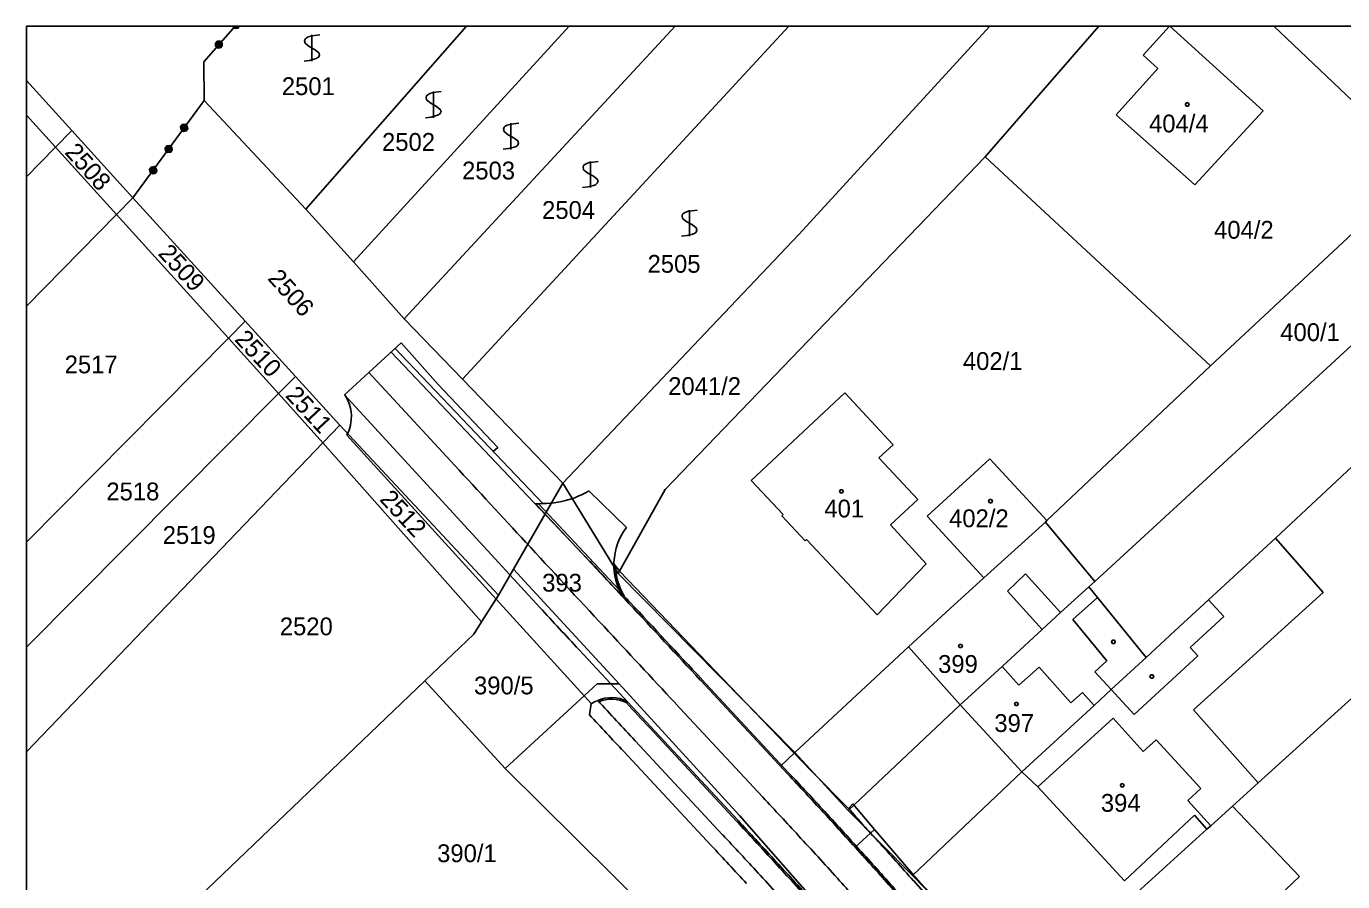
# Model space of a CAD drawing. Extents: x -639621 to -639329, y -1192893 to -1192488.
# Drawn here: x -639621.3 to -639495.6, y -1192569.5 to -1192487.8 of the extents above; entities that cross this region are included whole.
import ezdxf

# ---------------------------------------------------------------- set-up
doc = ezdxf.new("R2010")
doc.units = 0
for name, color, linetype in [('Vrstva 1', 7, 'Continuous'), ('Vrstva 19', 7, 'Continuous'), ('Vrstva 2', 7, 'Continuous'), ('Vrstva 20', 7, 'Continuous'), ('Vrstva 21', 7, 'Continuous'), ('Vrstva 22', 7, 'Continuous'), ('Vrstva 3', 7, 'Continuous'), ('Vrstva 4', 7, 'Continuous'), ('Vrstva 5', 7, 'Continuous'), ('Vrstva 61', 7, 'Continuous')]:
    doc.layers.add(name, color=color, linetype=linetype)

msp = doc.modelspace()

# ---------------------------------------------------------------- linework, layer by layer
at = {"layer": 'Vrstva 1'}
for p, q in [((-639601.33, -1192487.83), (-639604.33, -1192491.21)), ((-639579.25, -1192487.83), (-639594.57, -1192505.29)), ((-639590.01, -1192510.33), (-639569.44, -1192487.83)), ((-639585.18, -1192515.76), (-639559.3, -1192487.83)), ((-639548.46, -1192487.83), (-639579.63, -1192521.52)), ((-639547.5, -1192507.7), (-639529.28, -1192487.83)), ((-639529.73, -1192500.3), (-639518.86, -1192487.83)), ((-639512.13, -1192487.83), (-639514.63, -1192490.58)), ((-639503.19, -1192495.91), (-639512.08, -1192487.83)), ((-639502.15, -1192487.83), (-639487.95, -1192501.33)), ((-639514.63, -1192490.58), (-639513.22, -1192491.87)), ((-639604.33, -1192491.21), (-639604.27, -1192494.9)), ((-639513.22, -1192491.87), (-639517.21, -1192496.27)), ((-639616.93, -1192497.77), (-639621.26, -1192493.01)), ((-639611.08, -1192504.2), (-639604.27, -1192494.9)), ((-639604.27, -1192494.9), (-639594.57, -1192505.29)), ((-639509.7, -1192502.95), (-639503.19, -1192495.91)), ((-639457.17, -1192494.75), (-639502, -1192536.7)), ((-639621.26, -1192496.32), (-639618.49, -1192499.37)), ((-639517.21, -1192496.27), (-639509.7, -1192502.95)), ((-639618.49, -1192499.37), (-639616.93, -1192497.77)), ((-639611.08, -1192504.2), (-639616.93, -1192497.77)), ((-639618.49, -1192499.37), (-639621.26, -1192502.2)), ((-639618.49, -1192499.37), (-639612.65, -1192505.79)), ((-639529.73, -1192500.3), (-639560.27, -1192532.04)), ((-639529.73, -1192500.3), (-639508.19, -1192520.25)), ((-639508.19, -1192520.25), (-639487.95, -1192501.33)), ((-639612.65, -1192505.79), (-639611.08, -1192504.2)), ((-639600.36, -1192515.98), (-639611.08, -1192504.2)), ((-639621.26, -1192514.55), (-639612.65, -1192505.79)), ((-639612.65, -1192505.79), (-639601.96, -1192517.59)), ((-639594.57, -1192505.29), (-639590.01, -1192510.33)), ((-639519.26, -1192540.82), (-639482.08, -1192506.67)), ((-639570.05, -1192531.45), (-639547.5, -1192507.7)), ((-639590.01, -1192510.33), (-639585.18, -1192515.76)), ((-639601.96, -1192517.59), (-639600.36, -1192515.98)), ((-639595.57, -1192521.25), (-639600.36, -1192515.98)), ((-639579.63, -1192521.52), (-639585.18, -1192515.76)), ((-639601.96, -1192517.59), (-639621.26, -1192537.09)), ((-639601.96, -1192517.59), (-639597.2, -1192522.89)), ((-639523.82, -1192535.02), (-639508.19, -1192520.25)), ((-639597.2, -1192522.89), (-639595.57, -1192521.25)), ((-639591.33, -1192525.9), (-639595.57, -1192521.25)), ((-639579.63, -1192521.52), (-639570.05, -1192531.45)), ((-639621.26, -1192547.09), (-639597.2, -1192522.89)), ((-639597.2, -1192522.89), (-639592.96, -1192527.6)), ((-639543.13, -1192522.82), (-639552.05, -1192531.18)), ((-639538.51, -1192527.78), (-639543.13, -1192522.82)), ((-639591.33, -1192525.9), (-639592.96, -1192527.6)), ((-639576.18, -1192542.14), (-639591.33, -1192525.9)), ((-639592.96, -1192527.6), (-639621.26, -1192557.11)), ((-639577.8, -1192544.69), (-639592.96, -1192527.6)), ((-639539.86, -1192529.04), (-639538.51, -1192527.78)), ((-639536.15, -1192533.02), (-639539.86, -1192529.04)), ((-639535.25, -1192534.61), (-639529.27, -1192529.13)), ((-639529.27, -1192529.13), (-639523.82, -1192535.02)), ((-639570.05, -1192531.45), (-639574.76, -1192539.66)), ((-639564.74, -1192540.08), (-639570.05, -1192531.45)), ((-639560.27, -1192532.04), (-639564.74, -1192540.08)), ((-639552.05, -1192531.18), (-639548.99, -1192534.45)), ((-639538.75, -1192535.44), (-639536.15, -1192533.02)), ((-639548.99, -1192534.45), (-639549.12, -1192534.56)), ((-639549.12, -1192534.56), (-639546.9, -1192536.94)), ((-639529.84, -1192540.49), (-639535.25, -1192534.61)), ((-639535.35, -1192539.16), (-639538.75, -1192535.44)), ((-639529.84, -1192540.49), (-639523.97, -1192535.16)), ((-639523.97, -1192535.16), (-639523.82, -1192535.02)), ((-639523.97, -1192535.16), (-639519.26, -1192540.82)), ((-639546.77, -1192536.83), (-639546.9, -1192536.94)), ((-639546.77, -1192536.83), (-639540.04, -1192544.03)), ((-639502, -1192536.7), (-639508.39, -1192542.59)), ((-639502, -1192536.7), (-639497.45, -1192541.88)), ((-639574.76, -1192539.66), (-639576.18, -1192542.14)), ((-639574.76, -1192539.66), (-639573.32, -1192541.22)), ((-639540.04, -1192544.03), (-639535.35, -1192539.16)), ((-639547.9, -1192557.16), (-639564.74, -1192540.08)), ((-639533.05, -1192543.41), (-639529.84, -1192540.49)), ((-639519.83, -1192541.35), (-639519.26, -1192540.82)), ((-639576.18, -1192542.14), (-639577.8, -1192544.69)), ((-639564.65, -1192550.62), (-639573.32, -1192541.22)), ((-639522.51, -1192543.81), (-639519.83, -1192541.35)), ((-639519.83, -1192541.35), (-639519, -1192542.37)), ((-639519, -1192542.37), (-639514.35, -1192548.08)), ((-639509.82, -1192553.1), (-639497.45, -1192541.88)), ((-639537.05, -1192547.08), (-639533.05, -1192543.41)), ((-639508.39, -1192542.59), (-639511.62, -1192545.56)), ((-639577.8, -1192544.69), (-639578.54, -1192545.86)), ((-639524.28, -1192545.43), (-639522.51, -1192543.81)), ((-639578.54, -1192545.86), (-639583.2, -1192550.31)), ((-639528.1, -1192548.94), (-639524.28, -1192545.43)), ((-639511.62, -1192545.56), (-639514.35, -1192548.08)), ((-639503.65, -1192560.07), (-639487.05, -1192545.04)), ((-639547.9, -1192557.16), (-639537.05, -1192547.08)), ((-639514.35, -1192548.08), (-639517.68, -1192551.15)), ((-639532.09, -1192552.6), (-639528.1, -1192548.94)), ((-639583.2, -1192550.31), (-639621.26, -1192586.7)), ((-639583.2, -1192550.31), (-639575.54, -1192558.69)), ((-639575.54, -1192558.69), (-639566.76, -1192550.59)), ((-639564.65, -1192550.62), (-639566.76, -1192550.59)), ((-639553.16, -1192563.18), (-639564.65, -1192550.62)), ((-639517.68, -1192551.15), (-639519.32, -1192552.66)), ((-639542.8, -1192562.7), (-639532.09, -1192552.6)), ((-639519.32, -1192552.66), (-639526.21, -1192559.01)), ((-639503.65, -1192560.07), (-639509.82, -1192553.1)), ((-639542.8, -1192562.7), (-639547.9, -1192557.16)), ((-639561.85, -1192572.23), (-639575.54, -1192558.69)), ((-639526.21, -1192559.01), (-639536.67, -1192568.89)), ((-639526.21, -1192559.01), (-639524.7, -1192560.45)), ((-639524.7, -1192560.45), (-639516.41, -1192569.42)), ((-639506.1, -1192562.29), (-639503.65, -1192560.07)), ((-639508.17, -1192564.16), (-639506.1, -1192562.29)), ((-639506.1, -1192562.29), (-639499.72, -1192569.01)), ((-639534.95, -1192583.89), (-639553.16, -1192563.18)), ((-639536.67, -1192568.89), (-639542.8, -1192562.7)), ((-639516.41, -1192569.42), (-639509.74, -1192563.15)), ((-639508.54, -1192564.49), (-639509.74, -1192563.15)), ((-639515.21, -1192570.53), (-639508.54, -1192564.49)), ((-639508.54, -1192564.49), (-639508.17, -1192564.16)), ((-639525.7, -1192580.15), (-639536.67, -1192568.89)), ((-639499.72, -1192569.01), (-639502.36, -1192571.52))]:
    msp.add_line(p, q, dxfattribs=at)
for points in [[(-639601.06, -1192488.01), (-639601.33, -1192488.03), (-639601.53, -1192487.85), (-639601.53, -1192487.83)], [(-639601.49, -1192487.83), (-639601.49, -1192487.83), (-639601.49, -1192487.83)], [(-639601.28, -1192487.83), (-639601.37, -1192487.94), (-639601.43, -1192487.89), (-639601.38, -1192487.83)], [(-639601.06, -1192487.83), (-639601.2, -1192487.99), (-639601.31, -1192487.99), (-639601.17, -1192487.83)], [(-639600.9, -1192487.83), (-639601.06, -1192488.01), (-639601.08, -1192487.98), (-639600.95, -1192487.83)], [(-639602.73, -1192489.89), (-639603, -1192489.91), (-639603.2, -1192489.73), (-639603.21, -1192489.46), (-639603.04, -1192489.26), (-639602.77, -1192489.24), (-639602.57, -1192489.42), (-639602.55, -1192489.69), (-639602.73, -1192489.89), (-639602.73, -1192489.83), (-639602.57, -1192489.66), (-639602.59, -1192489.56), (-639602.84, -1192489.84), (-639602.96, -1192489.85), (-639602.61, -1192489.46), (-639602.67, -1192489.41), (-639603.02, -1192489.79), (-639603.08, -1192489.74), (-639602.73, -1192489.35), (-639602.79, -1192489.29), (-639603.13, -1192489.68), (-639603.16, -1192489.6), (-639602.89, -1192489.29), (-639602.98, -1192489.28), (-639603.14, -1192489.46)], [(-639606.37, -1192497.22), (-639606.1, -1192497.18), (-639605.89, -1192497.34), (-639605.84, -1192497.61), (-639606, -1192497.82), (-639606.27, -1192497.86), (-639606.49, -1192497.71), (-639606.53, -1192497.44), (-639606.37, -1192497.22), (-639606.36, -1192497.28), (-639606.5, -1192497.47), (-639606.47, -1192497.57), (-639606.25, -1192497.26), (-639606.14, -1192497.24), (-639606.44, -1192497.66), (-639606.38, -1192497.71), (-639606.07, -1192497.29), (-639606.01, -1192497.34), (-639606.31, -1192497.76), (-639606.26, -1192497.81), (-639605.95, -1192497.39), (-639605.91, -1192497.47), (-639606.15, -1192497.8), (-639606.06, -1192497.81), (-639605.91, -1192497.62)], [(-639607.85, -1192499.25), (-639607.58, -1192499.21), (-639607.37, -1192499.37), (-639607.33, -1192499.63), (-639607.48, -1192499.85), (-639607.75, -1192499.89), (-639607.97, -1192499.73), (-639608.01, -1192499.47), (-639607.85, -1192499.25), (-639607.82, -1192499.28), (-639607.97, -1192499.47), (-639607.95, -1192499.58), (-639607.71, -1192499.26), (-639607.6, -1192499.25), (-639607.93, -1192499.7), (-639607.87, -1192499.74), (-639607.54, -1192499.29), (-639607.47, -1192499.34), (-639607.8, -1192499.79), (-639607.74, -1192499.84), (-639607.41, -1192499.39), (-639607.39, -1192499.5), (-639607.63, -1192499.82), (-639607.51, -1192499.8), (-639607.37, -1192499.61)], [(-639609.33, -1192501.27), (-639609.07, -1192501.23), (-639608.85, -1192501.39), (-639608.81, -1192501.66), (-639608.97, -1192501.88), (-639609.23, -1192501.92), (-639609.45, -1192501.76), (-639609.49, -1192501.49), (-639609.33, -1192501.27), (-639609.3, -1192501.29), (-639609.44, -1192501.48), (-639609.42, -1192501.59), (-639609.18, -1192501.27), (-639609.08, -1192501.27), (-639609.4, -1192501.71), (-639609.34, -1192501.75), (-639609.02, -1192501.33), (-639608.95, -1192501.36), (-639609.27, -1192501.79), (-639609.2, -1192501.84), (-639608.89, -1192501.41), (-639608.85, -1192501.5), (-639609.11, -1192501.85), (-639609, -1192501.84), (-639608.84, -1192501.61)]]:
    msp.add_lwpolyline(points, dxfattribs=at)
at = {"layer": 'Vrstva 19'}
for p, q in [((-639590.87, -1192523.02), (-639585.47, -1192518.05)), ((-639567.46, -1192538.91), (-639586.43, -1192518.94)), ((-639571.96, -1192533.4), (-639586.06, -1192518.6)), ((-639572.22, -1192543.33), (-639590.87, -1192523.02)), ((-639571.96, -1192533.4), (-639572.64, -1192533.41)), ((-639572.64, -1192533.41), (-639564.32, -1192542.29)), ((-639572.36, -1192533.41), (-639572.62, -1192533.42)), ((-639572.51, -1192533.55), (-639564.93, -1192541.65)), ((-639572.36, -1192533.41), (-639564.64, -1192541.66)), ((-639564.64, -1192541.66), (-639564.32, -1192542.29)), ((-639548.56, -1192559.22), (-639556.91, -1192550.25)), ((-639556.91, -1192550.25), (-639548.56, -1192559.22)), ((-639563.9, -1192552.28), (-639563.99, -1192552.41)), ((-639561.67, -1192554.68), (-639553.31, -1192563.65)), ((-639554.78, -1192565.02), (-639554.77, -1192565.02))]:
    msp.add_line(p, q, dxfattribs=at)
for points in [[(-639585.47, -1192518.05), (-639581.94, -1192522.03), (-639576.25, -1192528.05), (-639576.7, -1192528.42)], [(-639580.36, -1192529.75), (-639588.55, -1192520.89)], [(-639550.93, -1192561.44), (-639559.29, -1192552.47)]]:
    msp.add_lwpolyline(points, dxfattribs=at)
for centre, radius, start, end in [((-632515.84, -1186006.86), 9615.38, 222.717281, 222.776868), ((-635904.09, -1189140.86), 4999.95, 222.78527, 222.91114), ((-635904.09, -1189140.86), 4996.7, 222.84821, 222.91114), ((-635904.09, -1189140.86), 5003.2, 222.84821, 222.91114), ((-632042.27, -1185548.31), 10271.17, 222.921457, 222.977225), ((-632043.17, -1185549.15), 10269.94, 222.921455, 222.977221), ((-632042.64, -1185548.66), 10273.91, 222.921456, 222.977224), ((-632043.17, -1185549.15), 10276.44, 222.921455, 222.977221), ((-640272.83, -1193235.04), 990.61, 42.72771, 43.01801), ((-640272.45, -1193234.69), 990.09, 42.7278, 43.0181), ((-640272.45, -1193234.69), 986.84, 42.7278, 43.0181), ((-640272.45, -1193234.69), 983.59, 42.7278, 43.0181), ((-639915.29, -1192904.24), 503.51, 42.0512, 42.6818), ((-639915.1, -1192904.07), 503.25, 42.0514, 42.682), ((-639915.1, -1192904.07), 500, 42.0514, 42.682), ((-639915.1, -1192904.07), 496.75, 42.0514, 42.682), ((-640296.6, -1193247.01), 1016.24, 41.71911, 42.00177), ((-640296.99, -1193247.36), 1016.76, 41.71905, 42.00171), ((-640296.99, -1193247.36), 1013.51, 41.71905, 42.00171)]:
    msp.add_arc(centre, radius, start, end, dxfattribs=at)
at = {"layer": 'Vrstva 20'}
for p, q in [((-639564.59, -1192539.87), (-639565.16, -1192539.15)), ((-639547.94, -1192557.24), (-639564.59, -1192539.87)), ((-639564.2, -1192542.2), (-639564.32, -1192542.29)), ((-639556.8, -1192550.15), (-639548.45, -1192559.12)), ((-639561.78, -1192554.78), (-639553.42, -1192563.76)), ((-639563.13, -1192556.04), (-639554.78, -1192565.02)), ((-639547.94, -1192557.24), (-639549.27, -1192558.46)), ((-639549.27, -1192558.46), (-639547.94, -1192557.24)), ((-639546.38, -1192558.84), (-639547.94, -1192557.24)), ((-639542.75, -1192562.5), (-639546.38, -1192558.84)), ((-639542.14, -1192566.19), (-639540.67, -1192564.85)), ((-639540.67, -1192564.85), (-639539.92, -1192565.65)), ((-639528.88, -1192578), (-639536.57, -1192569.39))]:
    msp.add_line(p, q, dxfattribs=at)
for centre, radius, start, end in [((-639559.21, -1192539.24), 5.8, 180.9853, 210.8121), ((-635904.09, -1189140.86), 4996.55, 222.90126, 222.91114), ((-632043.17, -1185549.15), 10269.79, 222.921455, 222.977221), ((-632043.17, -1185549.15), 10278.44, 222.948025, 222.977221), ((-639565.38, -1192555.15), 3.08, 63.2943, 113.2968), ((-632043.17, -1185549.15), 10276.59, 222.959102, 222.977221), ((-640272.45, -1193234.69), 990.24, 42.7278, 43.0181), ((-639471.86, -1192501.96), 93.22, 220.4993, 223.1007), ((-640272.45, -1193234.69), 983.44, 42.7278, 43.0181), ((-639915.1, -1192904.07), 503.4, 42.0514, 42.682), ((-640272.45, -1193234.69), 981.59, 42.7278, 43.0181), ((-640296.99, -1193247.36), 1018.76, 41.71905, 42.00171), ((-639915.1, -1192904.07), 496.6, 42.0514, 42.682), ((-640296.99, -1193247.36), 1016.91, 41.71905, 42.00171), ((-639915.1, -1192904.07), 494.75, 42.0514, 42.682)]:
    msp.add_arc(centre, radius, start, end, dxfattribs=at)
at = {"layer": 'Vrstva 21'}
for p, q in [((-639590.66, -1192526.86), (-639567.32, -1192552.49)), ((-639567.55, -1192532.19), (-639563.97, -1192535.67))]:
    msp.add_line(p, q, dxfattribs=at)
for centre, radius, start, end in [((-639593.93, -1192525.11), 3.71, 331.9131, 34.3094), ((-639572.02, -1192524.56), 8.84, 289.2691, 300.3567), ((-639572.02, -1192524.56), 8.84, 270.4205, 289.2691), ((-639559.21, -1192539.24), 5.95, 143.1133, 177.6349), ((-639559.21, -1192539.24), 5.95, 177.6349, 210.8121), ((-639565.69, -1192555.36), 3.3, 107.7054, 119.5413), ((-639565.38, -1192555.15), 3.23, 62.8122, 114.2453)]:
    msp.add_arc(centre, radius, start, end, dxfattribs=at)
at = {"layer": 'Vrstva 22'}
for p, q in [((-639542.35, -1192562.07), (-639542.75, -1192562.5)), ((-639540.28, -1192564.5), (-639542.35, -1192562.07)), ((-639540.67, -1192564.85), (-639540.28, -1192564.5))]:
    msp.add_line(p, q, dxfattribs=at)
for points in [[(-639567.32, -1192552.49), (-639567.5, -1192553.56)], [(-639555.87, -1192566.04), (-639564.23, -1192557.07)], [(-639540.67, -1192564.85), (-639540.28, -1192564.5), (-639536.66, -1192568.74), (-639535.53, -1192570), (-639527.39, -1192578.34), (-639528.06, -1192578.92)]]:
    msp.add_lwpolyline(points, dxfattribs=at)
for centre, radius, start, end in [((-632043.42, -1185549.39), 10279.6, 222.950471, 222.977222), ((-640271.67, -1193233.97), 979.03, 42.72798, 43.01828)]:
    msp.add_arc(centre, radius, start, end, dxfattribs=at)
at = {"layer": 'Vrstva 3'}
for points in [[(-639593.25, -1192488.66), (-639593.76, -1192488.72), (-639594.11, -1192488.77), (-639594.35, -1192488.85), (-639594.53, -1192488.96), (-639594.65, -1192489.05), (-639594.7, -1192489.22), (-639594.65, -1192489.45), (-639594.26, -1192489.77), (-639593.7, -1192490.08), (-639593.35, -1192490.35), (-639593.28, -1192490.55), (-639593.35, -1192490.75), (-639593.51, -1192490.88), (-639593.7, -1192490.95), (-639594.23, -1192491.08), (-639594.75, -1192491.15)], [(-639594, -1192491.16), (-639594, -1192489.89), (-639594, -1192488.66)], [(-639581.64, -1192494.07), (-639582.15, -1192494.13), (-639582.5, -1192494.18), (-639582.74, -1192494.26), (-639582.92, -1192494.37), (-639583.04, -1192494.46), (-639583.09, -1192494.63), (-639583.04, -1192494.86), (-639582.65, -1192495.18), (-639582.09, -1192495.49), (-639581.74, -1192495.76), (-639581.67, -1192495.96), (-639581.74, -1192496.16), (-639581.9, -1192496.29), (-639582.09, -1192496.36), (-639582.62, -1192496.49), (-639583.14, -1192496.56)], [(-639582.39, -1192496.57), (-639582.39, -1192495.3), (-639582.39, -1192494.07)], [(-639574.25, -1192497.08), (-639574.76, -1192497.14), (-639575.11, -1192497.19), (-639575.35, -1192497.27), (-639575.53, -1192497.38), (-639575.65, -1192497.47), (-639575.7, -1192497.64), (-639575.65, -1192497.87), (-639575.26, -1192498.19), (-639574.7, -1192498.5), (-639574.35, -1192498.77), (-639574.28, -1192498.97), (-639574.35, -1192499.17), (-639574.51, -1192499.3), (-639574.7, -1192499.37), (-639575.23, -1192499.5), (-639575.75, -1192499.57)], [(-639575, -1192499.58), (-639575, -1192498.31), (-639575, -1192497.08)], [(-639566.65, -1192500.73), (-639567.16, -1192500.79), (-639567.51, -1192500.84), (-639567.75, -1192500.92), (-639567.93, -1192501.03), (-639568.05, -1192501.12), (-639568.1, -1192501.29), (-639568.05, -1192501.52), (-639567.66, -1192501.84), (-639567.1, -1192502.15), (-639566.75, -1192502.42), (-639566.68, -1192502.62), (-639566.75, -1192502.82), (-639566.91, -1192502.95), (-639567.1, -1192503.02), (-639567.63, -1192503.15), (-639568.15, -1192503.22)], [(-639567.4, -1192503.23), (-639567.4, -1192501.96), (-639567.4, -1192500.73)], [(-639557.2, -1192505.38), (-639557.71, -1192505.44), (-639558.06, -1192505.49), (-639558.3, -1192505.57), (-639558.48, -1192505.68), (-639558.6, -1192505.77), (-639558.65, -1192505.94), (-639558.6, -1192506.17), (-639558.21, -1192506.49), (-639557.65, -1192506.8), (-639557.3, -1192507.07), (-639557.23, -1192507.27), (-639557.3, -1192507.47), (-639557.46, -1192507.6), (-639557.65, -1192507.67), (-639558.18, -1192507.8), (-639558.7, -1192507.87)], [(-639557.95, -1192507.88), (-639557.95, -1192506.61), (-639557.95, -1192505.38)]]:
    msp.add_lwpolyline(points, dxfattribs=at)
at = {"layer": 'Vrstva 4'}
for p, q in [((-639527.59, -1192541.75), (-639525.85, -1192540.09)), ((-639525.85, -1192540.09), (-639522.51, -1192543.81)), ((-639527.59, -1192541.75), (-639524.28, -1192545.43)), ((-639519, -1192542.37), (-639521.35, -1192544.47)), ((-639508.39, -1192542.59), (-639506.93, -1192544.18)), ((-639521.35, -1192544.47), (-639518.1, -1192548.42)), ((-639506.93, -1192544.18), (-639510.15, -1192547.15)), ((-639537.05, -1192547.08), (-639532.09, -1192552.6)), ((-639510.15, -1192547.15), (-639509.42, -1192547.94)), ((-639518.1, -1192548.42), (-639519.23, -1192549.47)), ((-639509.42, -1192547.94), (-639515.48, -1192553.53)), ((-639528.1, -1192548.94), (-639526.49, -1192550.74)), ((-639524.56, -1192549.02), (-639526.49, -1192550.74)), ((-639521.53, -1192552.42), (-639524.56, -1192549.02)), ((-639519.23, -1192549.47), (-639517.68, -1192551.15)), ((-639515.48, -1192553.53), (-639517.68, -1192551.15)), ((-639520.42, -1192551.42), (-639521.53, -1192552.42)), ((-639519.32, -1192552.66), (-639520.42, -1192551.42)), ((-639532.09, -1192552.6), (-639526.21, -1192559.01)), ((-639524.7, -1192560.45), (-639517.5, -1192553.89)), ((-639517.5, -1192553.89), (-639514.62, -1192557.05)), ((-639514.62, -1192557.05), (-639513.4, -1192555.94)), ((-639513.4, -1192555.94), (-639509.14, -1192560.6)), ((-639509.14, -1192560.6), (-639510.37, -1192561.73)), ((-639510.37, -1192561.73), (-639508.17, -1192564.16))]:
    msp.add_line(p, q, dxfattribs=at)
at = {"layer": 'Vrstva 5'}
for points in [[(-639510.33, -1192495.15), (-639510.24, -1192495.3), (-639510.33, -1192495.45), (-639510.51, -1192495.45), (-639510.6, -1192495.3), (-639510.51, -1192495.15)], [(-639543.35, -1192532.08), (-639543.26, -1192532.23), (-639543.35, -1192532.38), (-639543.53, -1192532.38), (-639543.62, -1192532.23), (-639543.53, -1192532.08)], [(-639529.12, -1192533.01), (-639529.03, -1192533.16), (-639529.12, -1192533.31), (-639529.3, -1192533.31), (-639529.39, -1192533.16), (-639529.3, -1192533.01)], [(-639531.98, -1192546.84), (-639531.89, -1192546.99), (-639531.98, -1192547.14), (-639532.16, -1192547.14), (-639532.25, -1192546.99), (-639532.16, -1192546.84)], [(-639517.38, -1192546.44), (-639517.29, -1192546.59), (-639517.38, -1192546.74), (-639517.56, -1192546.74), (-639517.65, -1192546.59), (-639517.56, -1192546.44)], [(-639513.71, -1192549.76), (-639513.62, -1192549.91), (-639513.71, -1192550.06), (-639513.89, -1192550.06), (-639513.98, -1192549.91), (-639513.89, -1192549.76)], [(-639526.64, -1192552.38), (-639526.55, -1192552.53), (-639526.64, -1192552.68), (-639526.82, -1192552.68), (-639526.91, -1192552.53), (-639526.82, -1192552.38)], [(-639516.54, -1192560.14), (-639516.45, -1192560.29), (-639516.54, -1192560.44), (-639516.72, -1192560.44), (-639516.81, -1192560.29), (-639516.72, -1192560.14)]]:
    msp.add_lwpolyline(points, close=True, dxfattribs=at)
at = {"layer": 'Vrstva 61'}
for points in [[(-639621.26, -1192893.33), (-639621.26, -1192487.83)], [(-639621.26, -1192487.83), (-639329.26, -1192487.83)]]:
    msp.add_lwpolyline(points, dxfattribs=at)

# ---------------------------------------------------------------- texts
at = {"layer": 'Vrstva 2'}
for s, p in [('2501', (-639596.87, -1192494.4)), ('404/4', (-639514.07, -1192497.96)), ('2502', (-639587.3, -1192499.72)), ('2503', (-639579.66, -1192502.45)), ('2504', (-639572.02, -1192506.22)), ('404/2', (-639507.86, -1192508.11)), ('2505', (-639561.95, -1192511.36)), ('400/1', (-639501.54, -1192517.88)), ('2517', (-639617.6, -1192520.96)), ('402/1', (-639531.84, -1192520.64)), ('2041/2', (-639559.98, -1192523.03)), ('2518', (-639613.62, -1192533.09)), ('401', (-639545.07, -1192534.72)), ('402/2', (-639533.16, -1192535.65)), ('2519', (-639608.24, -1192537.25)), ('393', (-639572.01, -1192541.8)), ('2520', (-639597.06, -1192545.97)), ('399', (-639534.21, -1192549.56)), ('390/5', (-639578.52, -1192551.61)), ('397', (-639528.84, -1192555.2)), ('394', (-639518.67, -1192562.82)), ('390/1', (-639582.04, -1192567.63))]:
    msp.add_text(s, height=1.7, dxfattribs=at).set_placement(p)
for s, rotation, p in [('2508', 311.8609, (-639617.68, -1192499.91)), ('2509', 312.7204, (-639608.76, -1192509.59)), ('2506', 312.0901, (-639598.3, -1192511.95)), ('2510', 313.1787, (-639601.46, -1192517.79)), ('2511', 312.835, (-639596.61, -1192523.14)), ('2512', 312.7777, (-639587.61, -1192533.05))]:
    msp.add_text(s, height=1.7, rotation=rotation, dxfattribs=at).set_placement(p)

doc.saveas('drawing.dxf')
